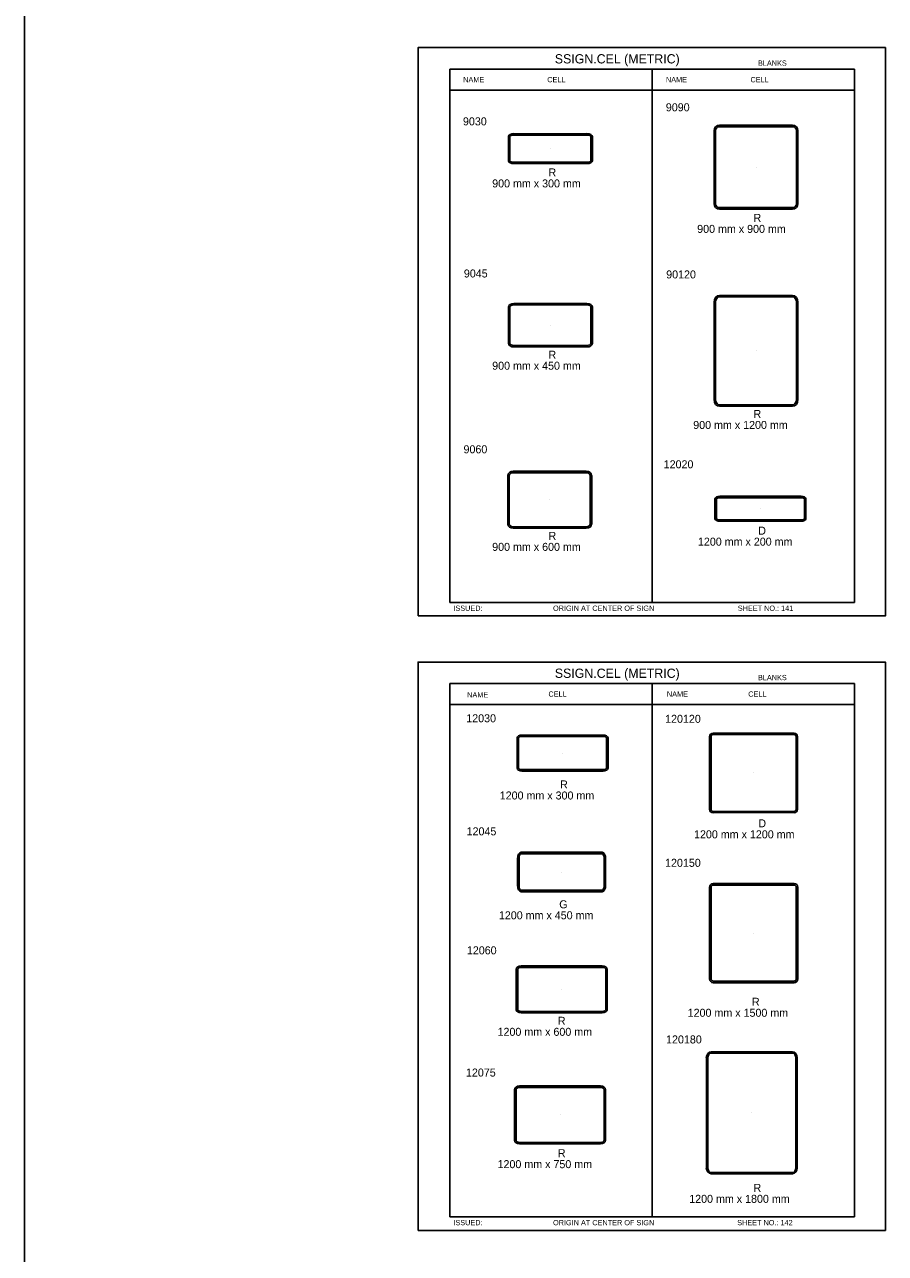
# Model space of a CAD drawing. Extents: x -12 to 6962, y -3756 to 679.
# Drawn here: x 1258.3 to 1581.2, y -3249.2 to -2788.5 of the extents above; entities that cross this region are included whole.
import ezdxf

# ---------------------------------------------------------------- set-up
doc = ezdxf.new("R2010")
doc.units = 0
for name, color, linetype in [('Level 1', 7, 'Continuous'), ('Level 2', 7, 'Continuous'), ('Level 3', 7, 'Continuous'), ('Level 60', 7, 'Continuous')]:
    doc.layers.add(name, color=color, linetype=linetype)

msp = doc.modelspace()

# ---------------------------------------------------------------- linework, layer by layer
at = {"layer": 'Level 1'}
for p, q in [((1569.58, -2805.13), (1417.83, -2805.13)), ((1417.83, -2805.13), (1417.83, -3005.13)), ((1493.71, -2805.13), (1493.71, -3005.13)), ((1569.58, -2805.13), (1569.58, -3005.13)), ((1569.58, -2813.04), (1417.83, -2813.04)), ((1455.56, -2834.96), (1455.56, -2834.96)), ((1532.67, -2841.91), (1532.67, -2841.91)), ((1455.56, -2901.17), (1455.56, -2901.17)), ((1532.67, -2910.78), (1532.67, -2910.78)), ((1455.3, -2966.6), (1455.3, -2966.6)), ((1534.35, -2969.98), (1534.35, -2969.98)), ((1417.83, -3005.13), (1569.58, -3005.13)), ((1569.58, -3035.48), (1417.83, -3035.48)), ((1417.83, -3035.48), (1417.83, -3235.48)), ((1493.71, -3035.48), (1493.71, -3235.48)), ((1569.58, -3035.48), (1569.58, -3235.48)), ((1569.58, -3043.4), (1417.83, -3043.4)), ((1460.1, -3061.55), (1460.1, -3061.55)), ((1531.76, -3069.02), (1531.76, -3069.02)), ((1459.77, -3106.17), (1459.77, -3106.17)), ((1531.8, -3129.08), (1531.8, -3129.08)), ((1459.81, -3150.17), (1459.81, -3150.17)), ((1459.17, -3197.24), (1459.17, -3197.24)), ((1531.1, -3196.43), (1531.1, -3196.43)), ((1417.83, -3235.48), (1569.58, -3235.48))]:
    msp.add_line(p, q, dxfattribs=at)
at = {"layer": 'Level 3'}
for p, q in [((1258.34, -1681.9), (1258.34, -3756.26)), ((1516.93, -2828.21), (1516.93, -2855.61)), ((1517.49, -2828.21), (1517.49, -2855.61)), ((1546.37, -2826.18), (1518.97, -2826.18)), ((1546.37, -2826.73), (1518.97, -2826.73)), ((1547.85, -2855.61), (1547.85, -2828.21)), ((1548.4, -2855.61), (1548.4, -2828.21)), ((1439.83, -2830.39), (1439.83, -2839.53)), ((1440.38, -2830.39), (1440.38, -2839.53)), ((1469.26, -2829.35), (1441.86, -2829.35)), ((1469.26, -2829.9), (1441.86, -2829.9)), ((1470.74, -2839.53), (1470.74, -2830.39)), ((1471.3, -2839.53), (1471.3, -2830.39)), ((1441.86, -2840.02), (1469.26, -2840.02)), ((1441.86, -2840.57), (1469.26, -2840.57)), ((1518.97, -2857.09), (1546.37, -2857.09)), ((1518.97, -2857.65), (1546.37, -2857.65)), ((1469.26, -2893.03), (1441.86, -2893.03)), ((1516.93, -2892.51), (1516.93, -2929.05)), ((1517.49, -2892.51), (1517.49, -2929.05)), ((1546.37, -2889.98), (1518.97, -2889.98)), ((1546.37, -2890.53), (1518.97, -2890.53)), ((1547.85, -2929.05), (1547.85, -2892.51)), ((1548.4, -2929.05), (1548.4, -2892.51)), ((1439.83, -2894.32), (1439.83, -2908.02)), ((1440.38, -2894.32), (1440.38, -2908.02)), ((1469.26, -2893.58), (1441.86, -2893.58)), ((1470.74, -2908.02), (1470.74, -2894.32)), ((1471.3, -2908.02), (1471.3, -2894.32)), ((1441.86, -2908.76), (1469.26, -2908.76)), ((1441.86, -2909.31), (1469.26, -2909.31)), ((1518.97, -2931.02), (1546.37, -2931.02)), ((1518.97, -2931.57), (1546.37, -2931.57)), ((1439.57, -2957.46), (1439.57, -2975.74)), ((1440.12, -2957.46), (1440.12, -2975.74)), ((1469, -2955.93), (1441.6, -2955.93)), ((1469, -2956.48), (1441.6, -2956.48)), ((1470.48, -2975.74), (1470.48, -2957.46)), ((1471.04, -2975.74), (1471.04, -2957.46)), ((1517.29, -2966.18), (1517.29, -2973.78)), ((1517.84, -2966.18), (1517.84, -2973.78)), ((1549.55, -2965.3), (1519.14, -2965.3)), ((1549.55, -2965.86), (1519.14, -2965.86)), ((1550.85, -2973.78), (1550.85, -2966.18)), ((1551.4, -2973.78), (1551.4, -2966.18)), ((1519.14, -2974.11), (1549.55, -2974.11)), ((1519.14, -2974.66), (1549.55, -2974.66)), ((1441.6, -2976.72), (1469, -2976.72)), ((1441.6, -2977.27), (1469, -2977.27)), ((1546.96, -3054.12), (1516.56, -3054.12)), ((1443.04, -3055.85), (1443.04, -3067.26)), ((1443.59, -3055.85), (1443.59, -3067.26)), ((1475.3, -3054.81), (1444.9, -3054.81)), ((1475.3, -3055.36), (1444.9, -3055.36)), ((1476.61, -3067.26), (1476.61, -3055.85)), ((1477.16, -3067.26), (1477.16, -3055.85)), ((1515.25, -3055.3), (1515.25, -3082.74)), ((1515.81, -3055.3), (1515.81, -3082.74)), ((1546.96, -3054.62), (1516.56, -3054.62)), ((1547.71, -3082.74), (1547.71, -3055.3)), ((1548.27, -3082.74), (1548.27, -3055.3)), ((1444.9, -3067.74), (1475.3, -3067.74)), ((1444.9, -3068.3), (1475.3, -3068.3)), ((1516.56, -3083.42), (1546.96, -3083.42)), ((1516.56, -3083.91), (1546.96, -3083.91)), ((1444.56, -3098.75), (1474.97, -3098.75)), ((1444.56, -3099.3), (1474.97, -3099.3)), ((1443.26, -3111.15), (1443.26, -3101.18)), ((1443.81, -3111.15), (1443.81, -3101.18)), ((1475.72, -3101.18), (1475.72, -3111.15)), ((1476.27, -3101.18), (1476.27, -3111.15)), ((1474.97, -3113.03), (1444.56, -3113.03)), ((1474.97, -3113.59), (1444.56, -3113.59)), ((1515.29, -3111.93), (1515.29, -3146.23)), ((1515.84, -3111.93), (1515.84, -3146.23)), ((1547, -3110.45), (1516.59, -3110.45)), ((1547, -3111.08), (1516.59, -3111.08)), ((1547.75, -3146.23), (1547.75, -3111.93)), ((1548.3, -3146.23), (1548.3, -3111.93)), ((1475.01, -3141.36), (1444.61, -3141.36)), ((1475.01, -3141.91), (1444.61, -3141.91)), ((1442.75, -3142.56), (1442.75, -3157.77)), ((1443.3, -3142.56), (1443.3, -3157.77)), ((1476.32, -3157.77), (1476.32, -3142.56)), ((1476.87, -3157.77), (1476.87, -3142.56)), ((1516.59, -3147.07), (1547, -3147.07)), ((1516.59, -3147.7), (1547, -3147.7)), ((1444.61, -3158.42), (1475.01, -3158.42)), ((1444.61, -3158.97), (1475.01, -3158.97)), ((1546.3, -3173.59), (1515.9, -3173.59)), ((1546.3, -3174.09), (1515.9, -3174.09)), ((1514.04, -3175.85), (1514.04, -3217.01)), ((1514.6, -3175.85), (1514.6, -3217.01)), ((1547.61, -3217.01), (1547.61, -3175.85)), ((1548.16, -3217.01), (1548.16, -3175.85)), ((1442.11, -3187.74), (1442.11, -3206.74)), ((1442.67, -3187.74), (1442.67, -3206.74)), ((1474.37, -3186.37), (1443.97, -3186.37)), ((1474.37, -3186.93), (1443.97, -3186.93)), ((1475.68, -3206.74), (1475.68, -3187.74)), ((1476.23, -3206.74), (1476.23, -3187.74)), ((1443.97, -3207.56), (1474.37, -3207.56)), ((1443.97, -3208.11), (1474.37, -3208.11)), ((1515.9, -3218.78), (1546.3, -3218.78)), ((1515.9, -3219.28), (1546.3, -3219.28))]:
    msp.add_line(p, q, dxfattribs=at)
for centre, radius, start, end in [((1518.97, -2828.21), 2.03, 90, 180), ((1518.97, -2828.21), 1.48, 90, 180), ((1546.37, -2828.21), 2.03, 0, 90), ((1546.37, -2828.21), 1.48, 0, 90), ((1518.97, -2855.61), 2.03, 180, 270), ((1518.97, -2855.61), 1.48, 180, 270), ((1546.37, -2855.61), 1.48, 270, 0), ((1546.37, -2855.61), 2.03, 270, 0)]:
    msp.add_arc(centre, radius, start, end, dxfattribs=at)
for centre, major_axis, ratio, start_param, end_param in [((1441.86, -2830.39), (-2.03, 0), 0.514853, 4.712389, 6.283185), ((1441.86, -2830.39), (-1.48, 0), 0.333333, 4.712389, 6.283185), ((1469.26, -2830.39), (-2.03, 0), 0.514853, 3.141593, 4.712389), ((1469.26, -2830.39), (-1.48, 0), 0.333333, 3.141593, 4.712389), ((1441.86, -2839.53), (2.03, 0), 0.514853, 3.141593, 4.712389), ((1441.86, -2839.53), (1.48, 0), 0.333333, 3.141593, 4.712389), ((1469.26, -2839.53), (1.48, 0), 0.333333, 4.712389, 6.283185), ((1469.26, -2839.53), (2.03, 0), 0.514853, 4.712389, 6.283185), ((1441.86, -2894.32), (-2.03, 0), 0.63614, 4.712389, 6.283185), ((1469.26, -2894.32), (-2.03, 0), 0.63614, 3.141593, 4.712389), ((1518.97, -2892.51), (0, -2.52), 0.804782, 3.141593, 4.712389), ((1518.97, -2892.51), (0, -1.97), 0.75, 3.141593, 4.712389), ((1546.37, -2892.51), (0, 2.52), 0.804782, 4.712389, 6.283185), ((1546.37, -2892.51), (0, 1.97), 0.75, 4.712389, 6.283185), ((1441.86, -2894.32), (-1.48, 0), 0.5, 4.712389, 6.283185), ((1469.26, -2894.32), (-1.48, 0), 0.5, 3.141593, 4.712389), ((1441.86, -2908.02), (2.03, 0), 0.63614, 3.141593, 4.712389), ((1441.86, -2908.02), (1.48, 0), 0.5, 3.141593, 4.712389), ((1469.26, -2908.02), (1.48, 0), 0.5, 4.712389, 6.283185), ((1469.26, -2908.02), (2.03, 0), 0.63614, 4.712389, 6.283185), ((1518.97, -2929.05), (0, -2.52), 0.804782, 4.712389, 6.283185), ((1518.97, -2929.05), (0, -1.97), 0.75, 4.712389, 6.283185), ((1546.37, -2929.05), (0, 1.97), 0.75, 3.141593, 4.712389), ((1546.37, -2929.05), (0, 2.52), 0.804782, 3.141593, 4.712389), ((1441.6, -2957.46), (-2.03, 0), 0.757427, 4.712389, 6.283185), ((1441.6, -2957.46), (-1.48, 0), 0.666667, 4.712389, 6.283185), ((1469, -2957.46), (-2.03, 0), 0.757427, 3.141593, 4.712389), ((1469, -2957.46), (-1.48, 0), 0.666667, 3.141593, 4.712389), ((1519.14, -2966.18), (-1.86, 0), 0.473248, 4.712389, 6.283185), ((1519.14, -2966.18), (-1.3, 0), 0.25, 4.712389, 6.283185), ((1549.55, -2966.18), (-1.86, 0), 0.473248, 3.141593, 4.712389), ((1549.55, -2966.18), (-1.3, 0), 0.25, 3.141593, 4.712389), ((1441.6, -2975.74), (2.03, 0), 0.757427, 3.141593, 4.712389), ((1441.6, -2975.74), (1.48, 0), 0.666667, 3.141593, 4.712389), ((1469, -2975.74), (1.48, 0), 0.666667, 4.712389, 6.283185), ((1469, -2975.74), (2.03, 0), 0.757427, 4.712389, 6.283185), ((1519.14, -2973.78), (1.86, 0), 0.473248, 3.141593, 4.712389), ((1519.14, -2973.78), (1.3, 0), 0.25, 3.141593, 4.712389), ((1549.55, -2973.78), (1.3, 0), 0.25, 4.712389, 6.283185), ((1549.55, -2973.78), (1.86, 0), 0.473248, 4.712389, 6.283185), ((1516.56, -3055.3), (-1.3, 0), 0.9025, 4.712389, 6.283185), ((1546.96, -3055.3), (-1.3, 0), 0.9025, 3.141593, 4.712389), ((1444.9, -3055.85), (-1.86, 0), 0.56104, 4.712389, 6.283185), ((1444.9, -3055.85), (-1.3, 0), 0.375, 4.712389, 6.283185), ((1475.3, -3055.85), (-1.86, 0), 0.56104, 3.141593, 4.712389), ((1475.3, -3055.85), (-1.3, 0), 0.375, 3.141593, 4.712389), ((1516.56, -3055.3), (-0.752, 0), 0.9025, 4.712389, 6.283185), ((1546.96, -3055.3), (-0.752, 0), 0.9025, 3.141593, 4.712389), ((1444.9, -3067.26), (1.86, 0), 0.56104, 3.141593, 4.712389), ((1444.9, -3067.26), (1.3, 0), 0.375, 3.141593, 4.712389), ((1475.3, -3067.26), (1.3, 0), 0.375, 4.712389, 6.283185), ((1475.3, -3067.26), (1.86, 0), 0.56104, 4.712389, 6.283185), ((1516.56, -3082.74), (1.3, 0), 0.9025, 3.141593, 4.712389), ((1516.56, -3082.74), (0.752, 0), 0.9025, 3.141593, 4.712389), ((1546.96, -3082.74), (0.752, 0), 0.9025, 4.712389, 6.283185), ((1546.96, -3082.74), (1.3, 0), 0.9025, 4.712389, 6.283185), ((1444.56, -3101.18), (0, -2.43), 0.536402, 3.141593, 4.712389), ((1444.56, -3101.18), (0, -1.88), 0.4, 3.141593, 4.712389), ((1474.97, -3101.18), (0, 2.43), 0.536402, 4.712389, 6.283185), ((1474.97, -3101.18), (0, 1.88), 0.4, 4.712389, 6.283185), ((1444.56, -3111.15), (0, -2.43), 0.536402, 4.712389, 6.283185), ((1444.56, -3111.15), (0, -1.88), 0.4, 4.712389, 6.283185), ((1474.97, -3111.15), (0, 1.88), 0.4, 3.141593, 4.712389), ((1474.97, -3111.15), (0, 2.43), 0.536402, 3.141593, 4.712389), ((1516.59, -3111.93), (0, -1.47), 0.886427, 3.141593, 4.712389), ((1516.59, -3111.93), (0, -0.848), 0.886427, 3.141593, 4.712389), ((1547, -3111.93), (0, 1.47), 0.886427, 4.712389, 6.283185), ((1547, -3111.93), (0, 0.848), 0.886427, 4.712389, 6.283185), ((1444.61, -3142.56), (-1.86, 0), 0.648832, 4.712389, 6.283185), ((1444.61, -3142.56), (-1.3, 0), 0.5, 4.712389, 6.283185), ((1475.01, -3142.56), (-1.86, 0), 0.648832, 3.141593, 4.712389), ((1475.01, -3142.56), (-1.3, 0), 0.5, 3.141593, 4.712389), ((1516.59, -3146.23), (0, -1.47), 0.886427, 4.712389, 6.283185), ((1516.59, -3146.23), (0, -0.848), 0.886427, 4.712389, 6.283185), ((1547, -3146.23), (0, 0.848), 0.886427, 3.141593, 4.712389), ((1547, -3146.23), (0, 1.47), 0.886427, 3.141593, 4.712389), ((1444.61, -3157.77), (1.86, 0), 0.648832, 3.141593, 4.712389), ((1444.61, -3157.77), (1.3, 0), 0.5, 3.141593, 4.712389), ((1475.01, -3157.77), (1.3, 0), 0.5, 4.712389, 6.283185), ((1475.01, -3157.77), (1.86, 0), 0.648832, 4.712389, 6.283185), ((1515.9, -3175.85), (0, -2.27), 0.820056, 3.141593, 4.712389), ((1515.9, -3175.85), (0, -1.77), 0.738689, 3.141593, 4.712389), ((1546.3, -3175.85), (0, 2.27), 0.820056, 4.712389, 6.283185), ((1546.3, -3175.85), (0, 1.77), 0.738689, 4.712389, 6.283185), ((1443.97, -3187.74), (-1.86, 0), 0.736624, 4.712389, 6.283185), ((1443.97, -3187.74), (-1.3, 0), 0.625, 4.712389, 6.283185), ((1474.37, -3187.74), (-1.86, 0), 0.736624, 3.141593, 4.712389), ((1474.37, -3187.74), (-1.3, 0), 0.625, 3.141593, 4.712389), ((1443.97, -3206.74), (1.86, 0), 0.736624, 3.141593, 4.712389), ((1443.97, -3206.74), (1.3, 0), 0.625, 3.141593, 4.712389), ((1474.37, -3206.74), (1.3, 0), 0.625, 4.712389, 6.283185), ((1474.37, -3206.74), (1.86, 0), 0.736624, 4.712389, 6.283185), ((1515.9, -3217.01), (0, -2.27), 0.820056, 4.712389, 6.283185), ((1515.9, -3217.01), (0, -1.77), 0.738689, 4.712389, 6.283185), ((1546.3, -3217.01), (0, 1.77), 0.738689, 3.141593, 4.712389), ((1546.3, -3217.01), (0, 2.27), 0.820056, 3.141593, 4.712389)]:
    msp.add_ellipse(centre, major_axis=major_axis, ratio=ratio, start_param=start_param, end_param=end_param, dxfattribs=at)
at = {"layer": 'Level 60'}
for points in [[(1405.95, -3010.17), (1581.21, -3010.17), (1581.21, -2797.08), (1405.95, -2797.08)], [(1405.95, -3240.53), (1581.21, -3240.53), (1581.21, -3027.43), (1405.95, -3027.43)]]:
    msp.add_lwpolyline(points, close=True, dxfattribs=at)

# ---------------------------------------------------------------- texts
at = {"layer": 'Level 2'}
for s, p in [('9090', (1498.85, -2820.96)), ('9030', (1422.76, -2826.24)), ('9045', (1423.1, -2883.26)), ('90120', (1498.98, -2883.62)), ('9060', (1422.97, -2949.18)), ('12020', (1498.04, -2954.8)), ('12030', (1424, -3050.03)), ('120120', (1498.58, -3050.23)), ('12045', (1424.13, -3092.41)), ('120150', (1498.56, -3104.21)), ('12060', (1424.23, -3137.03)), ('120180', (1498.94, -3170.43)), ('12075', (1423.89, -3182.84))]:
    msp.add_text(s, height=3, dxfattribs=at).set_placement(p)
at = {"layer": 'Level 3'}
for s, height, p in [('SSIGN.CEL (METRIC)', 3.4642, (1457.21, -2803.02)), ('BLANKS', 1.979, (1533.42, -2803.89)), ('NAME', 1.98, (1422.85, -2810.08)), ('CELL', 1.98, (1454.39, -2810.08)), ('NAME', 1.98, (1498.89, -2810.08)), ('CELL', 1.98, (1530.6, -2810.08)), ('R', 3, (1454.85, -2845.38)), ('900 mm x 300 mm', 3, (1433.72, -2849.5)), ('R', 3, (1531.75, -2862.43)), ('900 mm x 900 mm', 3, (1510.61, -2866.55)), ('R', 3, (1454.85, -2913.73)), ('900 mm x 450 mm', 3, (1433.72, -2917.85)), ('R', 3, (1531.75, -2935.94)), ('900 mm x 1200 mm', 3, (1509.12, -2940.06)), ('R', 3, (1454.85, -2981.63)), ('D', 3, (1533.51, -2979.69)), ('900 mm x 600 mm', 3, (1433.72, -2985.76)), ('1200 mm x 200 mm', 3, (1510.89, -2983.81)), ('ISSUED:', 1.98, (1419.17, -3008.25)), ('ORIGIN AT CENTER OF SIGN', 1.9795, (1456.55, -3008.25)), ('SHEET NO.: 141', 1.9795, (1525.84, -3008.25)), ('SSIGN.CEL (METRIC)', 3.4642, (1457.21, -3033.37)), ('BLANKS', 1.979, (1533.42, -3034.24)), ('NAME', 1.98, (1424.34, -3040.73)), ('CELL', 1.98, (1454.82, -3040.44)), ('NAME', 1.98, (1499.25, -3040.44)), ('CELL', 1.98, (1529.76, -3040.44)), ('R', 3, (1459.18, -3074.84)), ('1200 mm x 300 mm', 3, (1436.55, -3078.97)), ('D', 3, (1533.54, -3089.41)), ('1200 mm x 1200 mm', 3, (1509.43, -3093.53)), ('G', 3, (1458.87, -3119.77)), ('1200 mm x 450 mm', 3, (1436.24, -3123.89)), ('R', 3, (1531.15, -3156.31)), ('1200 mm x 1500 mm', 3, (1507.04, -3160.43)), ('1200 mm x 600 mm', 3, (1435.74, -3167.57)), ('R', 3, (1458.36, -3163.45)), ('R', 3, (1458.36, -3213.07)), ('1200 mm x 750 mm', 3, (1435.74, -3217.19)), ('R', 3, (1531.74, -3226.07)), ('1200 mm x 1800 mm', 3, (1507.62, -3230.19)), ('ISSUED:', 1.98, (1419.17, -3238.6)), ('ORIGIN AT CENTER OF SIGN', 1.9795, (1456.55, -3238.6)), ('SHEET NO.: 142', 1.9795, (1525.61, -3238.6))]:
    msp.add_text(s, height=height, dxfattribs=at).set_placement(p)

doc.saveas('drawing.dxf')
